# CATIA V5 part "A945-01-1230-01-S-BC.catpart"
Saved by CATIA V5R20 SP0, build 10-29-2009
Part number: A945-01-1230-01-S-BC
Source: Unknown
Property "ARTICLENO": "A945-01-1230-01-S-BC"
Property "B": "125.000"
Property "BOMINFO": "A945-01-1230-01-S-BC"
Property "CODE": "A945-01-1230-01-S-BC"
Property "D1": "26.000"
Property "D2": "17.500"
Property "D5": "20.000"
Property "D6": "16.000"
Property "H": "57.000"
Property "H1": "44.000"
Property "H2": "60.000"
Property "H3": "28.000"
Property "L1": "300.000"
Property "L2": "25.000"
Property "L3": "125.000"
Property "L4": "125.000"
Property "L5": "55.000"
Property "L6": "195.000"
Property "LINA": "A945-01-1230-01-S-BC"
Property "N": "8.000"
Property "NB": "A945-01-1230-01-S-BC"
Property "NBSYN": " $CODE."
Property "NN": "A945-01"
Property "NT": "v driver sets replaceable inserts pisitive return"
Property "SUPPLIER": "CF"
Property "Z": "85.000"
Bounding box of the stored display mesh (mm): x -669.473 to -511.473, y 748.188 to 833.188, z 0 to 300
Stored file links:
  C:\Users\Utente\Desktop\3D files A945-01\A945-01-1230-01-S-BC.catpart
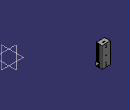
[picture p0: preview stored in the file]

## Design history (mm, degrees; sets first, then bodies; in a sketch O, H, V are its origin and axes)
Body1 "Geometry.1" (main body)
  Solid1 "A945-01-1230-01-S-BC.catpart": solid without history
